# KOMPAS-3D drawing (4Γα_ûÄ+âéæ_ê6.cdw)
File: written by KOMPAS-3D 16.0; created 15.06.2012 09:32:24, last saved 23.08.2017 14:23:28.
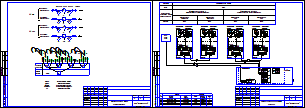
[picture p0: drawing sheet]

Sheets 1-2: A3, landscape

Title block, sheet 1: name: Руководство по эксплуатации; sheet number: 1; sheets: 27; organisation: ООО"Интелприбор"; sheet format: A3; stored path: W:\Users\smirnov_v\Desktop\шаблоны\4-х трубка\4-х трубка ГВС-max.cdw / D:\Проекты\Лыткарино\ул. Квартал 3А, д.25\710.74 РП.cdw; file name: 4-х трубка ГВС-max.cdw / 710.74 РП.cdw; cell 51: МО, Воскресенсикй р-н, п. Хорлово, ул. Интернациональная, д. 4; cell 320: Р
Title block, sheet 2: sheet number: 2

Views: Вид 2, Вид 3
Referenced files in C:\Program Files (x86)\ASCON\KOMPAS-3D V16\Sys\: spds.lcs, EngSys.lcs, GRAPHIC.LHS
Referenced files: graphic.tdp
Referenced files in W:\Users\smirnov_v\Desktop\шаблоны\4-х трубка\: 4-х трубка ГВС-max.cdw
Referenced files in D:\Проекты\Лыткарино\ул. Квартал 3А, д.25\: 710.74 РП.cdw
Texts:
  Смирнов В.С.
  УУ-3423
  GOST Common
  Normal
  List Paragraph
  heading 3
  для схемы
  txt
  Т0-элементы
  ВРУ
  Преобразователь расхода
  Термопреобразователь
  Преобразователь давления
  Преобразователь цифровой
  Системный блок МКТС
  Агрегат
  Системный блок  МКТС
  Среда
  Вода
  параметра и место
  отбора импульса
  Учет тепловой энергии и
  теплоносителя системы отопления
  Подающий
  трубопровод
  отопления
  Обратный
  расхода горячей воды системы ГВС
  ГВС
  ИМ1
  ИМ2
  ИМ3
  ИМ4
  приборы
  по месту
  шкаф
  учета
  UQIES
  УУГВС
  УУТЭ
  Функциональная схема
  Плата подключений
  СБ МКТС
  каб.
  Начало
  трассы
  Трассы
  Марка
  Проложен
  Изм. модуль (Т1)
  Изм. модуль (Т2)
  Изм. модуль (Т3)
  Изм. модуль (Т4)
  ВРУ 220В, 50 Гц
  ИМ (Т1)
  ИМ (Т3)
  FTP
  ПВС
  Конец
  Кол-во и
  сеч. жил
  Длина,
  UP+
  UP-
  ИМП
  Лин
  Измерительный
  модуль М121
  Pt 100
  Преобразователь
  температуры
  давления
  Размеры, параметризация
  сит. план
  подача ГВС
  обратка ГВС
  хвс
  обратка
  POLYLINE_STYLE_0.25_RGB_0_0_0
  стены
  Основная (не является границей для штриховки)
  POLYLINE_STYLE_0.18_RGB_0_0_0
  ХВС
  зеленая
  Красная тонкая
  арматура
  Подача
  Скрытая линия
  Ось Z
  Ось Y
  Ось X
  Образующая трубопровода (проектируемого)
  Трубопровод толщиной 0.6мм (одна линия)
  Трубопровод толщиной 1.2мм (одна линия)
  Трубопровод толщиной 1.0мм (одна линия)
  Трубопровод толщиной 0.8мм (одна линия)
  Трубопровод существующий (одна линия)
  Трубопровод невидимый (одна линия)
  Трубопровод демонтируемый (одна линия)
  Осевая трубопровода
  Осевая трубопровода (демонтируемого)
  Образующая трубопровода (существующего)
  Образующая трубопровода (невидимого)
  Изолированный трубопровод проектируемый (одна линия)
  Изолированный трубопровод существующий (одна линия)
  Образующая изоляции
  Изоляция
  Изолированный трубопровод невидимый (одна линия)
  Штрих пвс 075
  штрих пвс 2,5
  существующее оборудование
  Существующее оборудование
  K5LT_BASIC_RGB_0_0_255_THICK_0.53
  POLYLINE_STYLE_1.51_RGB_0_0_255
  POLYLINE_STYLE_0.50_RGB_128_128_128
  K5LT_AXLED_RGB_255_128_0_SC_1_THICK_0.18
  ACAD_ISO04W100_RGB_0_0_0_SC_1_THICK_0.18
  тонкая черная
  тонкая красная
  тонкая синяя
  тонкая оранж
  красн штрих
  пломбировка
  Провода
  синий штрих
  Стили документа
  G2co
  расход вторичной воды объемный
  расход вторичной воды объемный при 70гр
  Gco
  расход теплоносителя массовый
  расход теплоносит объемн подающ
  расход теплоносит объемн обр
  Лапир
  Ghvs
  Im1
  Im2
  Im3
  Im4
  Im5
  Khvs
  норматив ХВС
  число подъездов
  число этажей
  Nkv
  число квартир
  тепловая нагрузка на отопление
  сумма Q
  Qgvs
  тепловая нагрузка ГВС
  тепловая нагрузка на циркуляцию ГВС
  иммитовставка или под манометр
  ro1
  ro2
  ro3
  ro4
  верх предел темп граф
  нижн предел темп граф
  темп подачи ГВС
  темп обр ГВС
  темр хол воды
  vzdh
  Kchn
  Ktp
  Knp
  tnv
  Vклап
  KLP
  RPD
  RDS
  PUMP
  ro5
  beta
  tnv98
  Shifr
  Переход ГОСТ 17378-2001
  Переход
  ГОСТ
  Сталь 09Г2С ГОСТ 19281-89
  Втулка 20x50
  Лит-Масса-Масштаб
  Материал-Предприятие
  Title Specification
  Body Specification ( left align )
  Body Specificaton ( centered )
  Поз.
  Кол.
  Приме-
  чание
  Таблица спецификации
  Засыпка
  Штрих3
  Штрих2
  Штрих1
  Песок
  Штр0.5пр7
  Штр0.5пр12
  Штр0.3пр10
  Штр1.4пр21.21
  Штр1пр15
  Штр2.12пр35
  Штр1.5пр25
  Штр2.82пр42.42
  Штр2пр30
  SACNCR_ISO 1
  Электрощитовая
  Пр-1
  Ок-1
  Обозначение стандарта
  Типоразмер
  Пояснительная записка
  автоматизации
  Рабочие чертежи основного комплекта. ГОСТ Р 21.1101-2009 Ф3
  Стадия
  Лист
  Листов
  Изм.
  Кол.уч.
  №док.
  Подп.
  Дата
  Разраб.
  Пров.
  Т.контр.
  Н.контр.
  Утв.
  Изменение
  Номер документа
  Подпись
  Наименование объекта строительства, в состав которого входит здание, наим. микр
  Наименование здания (сооружения)
  Порядковый номер листа
  Количество листов в документе
  Наименование изображения
  Индекс предприятия, выпускающего документ
  Инв. № подл.
  Подп. и дата
  Взам. инв. №
  Инвентарный номер подлинника
  Подпись принявшего подлинник на хранение
  Инвентарный номер подлинника, взамен которого выпущен данный подлинник
  Согласовано
  Формат листа
  Согласование
  03 Рабочие чертежи основного комплекта. ГОСТ Р 21.1101-2009 Ф3
  Схема соединений внешних
  проводок
Dimensions and other numbers on the sheet: 220В; 50Гц; 17; 2; 4; 1,2,3,4; 5,6,7,8; 9,10,11,12; 13,14,15,16; 6; 5; 1; 3; 10; 13; 14; 9; 15; 0; 5,0; 3,2388; 0,0400; 40; 95; 3,1876; 4,5; 0,0; 0,0000; 70; 11; 12; 7; 8; 16; 2x2x0,52; 3х0,75; 20; 4-20; 09Г2С; 27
